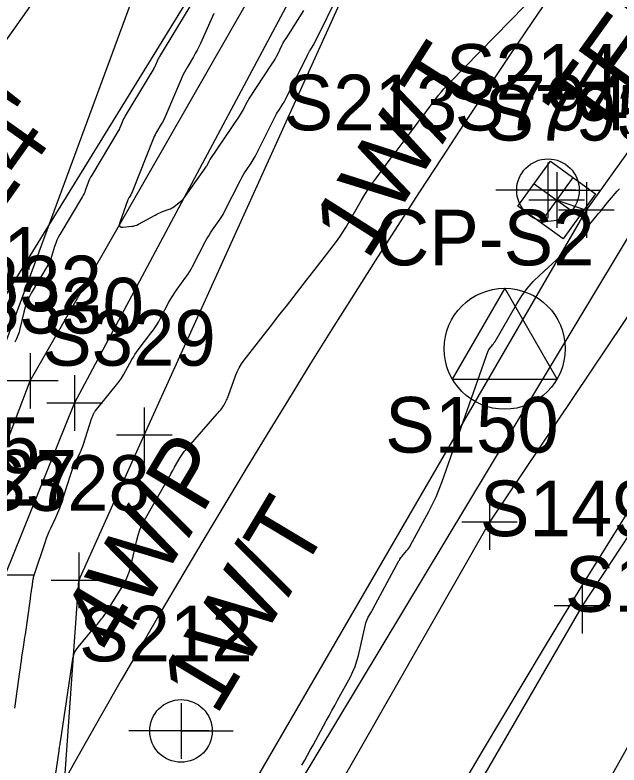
# Model space of a CAD drawing. Extents: x 816928 to 825690, y 436959 to 448212.
# Drawn here: x 818891.9 to 818935.3, y 445110 to 445164 of the extents above; entities that cross this region are included whole.
import ezdxf

# ---------------------------------------------------------------- set-up
doc = ezdxf.new("R2010")
doc.units = 0
for name, color, linetype in [('SURVEY - CENTERLINE - Preliminary', 7, 'Continuous'), ('SURVEY - CONTOURS - Index with Text', 7, 'Continuous'), ('SURVEY - CONTOURS - Intermediate with optional Text', 7, 'Continuous'), ('SURVEY - CONTROL with Text', 7, 'Continuous'), ('SURVEY - DRAINAGE - Area Shapes', 7, 'Continuous'), ('SURVEY - DRAINAGE - Bridges Text', 7, 'Continuous'), ('SURVEY - DTM - Breaklines', 7, 'Continuous'), ('SURVEY - DTM - Breaklines - Points - Locators', 7, 'Continuous'), ('SURVEY - DTM - Breaklines - Points - Numbers', 7, 'Continuous'), ('SURVEY - PROPERTY - Parcels', 7, 'Continuous'), ('SURVEY - PROPERTY - ROW Lines', 7, 'Continuous'), ('SURVEY - TRANSPORTATION - Roads', 7, 'Continuous'), ('SURVEY - TRANSPORTATION - Roads - Points - Locators', 7, 'Continuous'), ('SURVEY - TRANSPORTATION - Roads - Points - Numbers', 7, 'Continuous'), ('SURVEY - UTILITIES - Gas with Text', 7, 'Continuous'), ('SURVEY - UTILITIES - Poles and Miscellaneous - Points - Locators', 7, 'Continuous'), ('SURVEY - UTILITIES - Poles and Miscellaneous - Points - Numbers', 7, 'Continuous'), ('SURVEY - UTILITIES - Poles and Miscellaneous with Text', 7, 'Continuous'), ('SURVEY - UTILITIES - Telephone (Underground) - Points - Locators', 7, 'Continuous'), ('SURVEY - UTILITIES - Telephone (Underground) - Points - Numbers', 7, 'Continuous'), ('SURVEY - UTILITIES - Telephone (Underground) with Text', 7, 'Continuous'), ('SURVEY - VEGETATION - Features with Text', 7, 'Continuous')]:
    doc.layers.add(name, color=color, linetype=linetype)

msp = doc.modelspace()

# ---------------------------------------------------------------- linework, layer by layer
at = {"layer": 'SURVEY - CENTERLINE - Preliminary'}
msp.add_arc((819561.099, 444735.998), 738, 144.598464, 158.728454, dxfattribs=at)
msp.add_arc((819561.099, 444735.998), 738, 144.598464, 158.728454, dxfattribs=at)
at = {"layer": 'SURVEY - CONTOURS - Index with Text'}
msp.add_lwpolyline([(818894.431, 445106.853), (818895.057, 445111.046), (818895.067, 445111.111), (818895.076, 445111.176), (818895.086, 445111.241), (818895.095, 445111.307), (818895.125, 445111.52), (818895.131, 445111.566), (818895.138, 445111.612), (818895.145, 445111.657), (818895.151, 445111.703), (818895.85, 445116.369), (818895.853, 445116.386), (818895.855, 445116.403), (818895.858, 445116.42), (818895.86, 445116.437), (818895.868, 445116.494), (818895.87, 445116.506), (818895.872, 445116.518), (818895.874, 445116.53), (818895.875, 445116.542), (818896.044, 445117.663), (818896.095, 445117.897), (818896.176, 445118.117), (818896.287, 445118.323), (818896.428, 445118.517), (818897.433, 445119.72), (818897.528, 445119.833), (818897.623, 445119.947), (818897.717, 445120.06), (818897.812, 445120.173), (818898.121, 445120.543), (818898.186, 445120.623), (818898.248, 445120.706), (818898.308, 445120.79), (818898.365, 445120.876), (818899.535, 445122.721), (818899.768, 445123.124), (818899.963, 445123.543), (818900.122, 445123.976), (818900.244, 445124.425), (818900.645, 445126.195), (818900.744, 445126.569), (818900.87, 445126.933), (818901.023, 445127.286), (818901.202, 445127.629), (818902.934, 445130.658), (818902.978, 445130.735), (818903.021, 445130.812), (818903.064, 445130.89), (818903.107, 445130.968), (818903.244, 445131.223), (818903.274, 445131.278), (818903.304, 445131.332), (818903.334, 445131.386), (818903.365, 445131.44), (818903.766, 445132.142), (818903.855, 445132.29), (818903.952, 445132.433), (818904.056, 445132.57), (818904.167, 445132.703), (818906.606, 445135.469), (818906.689, 445135.569), (818906.766, 445135.673), (818906.838, 445135.781), (818906.903, 445135.893), (818907.105, 445136.267), (818907.147, 445136.348), (818907.185, 445136.43), (818907.221, 445136.514), (818907.253, 445136.599), (818907.753, 445138.018), (818907.872, 445138.316), (818908.013, 445138.601), (818908.177, 445138.874), (818908.364, 445139.134), (818910.002, 445141.234), (818910.353, 445141.684), (818910.704, 445142.134), (818911.055, 445142.584), (818911.406, 445143.035), (818912.607, 445144.574), (818912.865, 445144.904), (818913.122, 445145.234), (818913.38, 445145.564), (818913.637, 445145.894), (818914.783, 445147.363), (818915.023, 445147.682), (818915.251, 445148.008), (818915.468, 445148.342), (818915.674, 445148.683), (818916.81, 445150.643), (818917.059, 445151.059), (818917.321, 445151.467), (818917.595, 445151.866), (818917.881, 445152.258), (818918.882, 445153.585), (818919.096, 445153.869), (818919.31, 445154.154), (818919.525, 445154.438), (818919.739, 445154.722), (818920.695, 445155.99), (818920.9, 445156.262), (818921.105, 445156.534), (818921.31, 445156.805), (818921.514, 445157.077), (818922.354, 445158.191), (818922.538, 445158.426), (818922.729, 445158.655), (818922.927, 445158.878), (818923.133, 445159.094), (818928.598, 445164.656)], dxfattribs=at)
at = {"layer": 'SURVEY - CONTOURS - Intermediate with optional Text'}
for points in [[(818891.866, 445114.122), (818891.89, 445114.292), (818892.234, 445116.73), (818892.272, 445116.997), (818892.311, 445117.265), (818892.35, 445117.532), (818892.39, 445117.799), (818892.521, 445118.672), (818892.549, 445118.86), (818892.577, 445119.047), (818892.604, 445119.234), (818892.631, 445119.421), (818892.993, 445121.987), (818893.007, 445122.091), (818893.022, 445122.194), (818893.038, 445122.298), (818893.053, 445122.402), (818893.104, 445122.74), (818893.115, 445122.813), (818893.126, 445122.885), (818893.136, 445122.958), (818893.147, 445123.03), (818893.198, 445123.392), (818893.211, 445123.469), (818893.227, 445123.546), (818893.246, 445123.621), (818893.269, 445123.696), (818894.074, 445126.099), (818894.161, 445126.345), (818894.255, 445126.588), (818894.356, 445126.829), (818894.465, 445127.066), (818894.832, 445127.836), (818894.908, 445128.002), (818894.979, 445128.171), (818895.044, 445128.341), (818895.103, 445128.514), (818895.896, 445130.945), (818895.972, 445131.166), (818896.056, 445131.384), (818896.146, 445131.599), (818896.244, 445131.811), (818896.574, 445132.498), (818896.642, 445132.647), (818896.705, 445132.797), (818896.762, 445132.95), (818896.814, 445133.105), (818897.387, 445134.918), (818897.407, 445134.976), (818897.428, 445135.034), (818897.452, 445135.09), (818897.477, 445135.146), (818897.565, 445135.326), (818897.584, 445135.364), (818897.606, 445135.4), (818897.63, 445135.436), (818897.656, 445135.47), (818899.196, 445137.377), (818899.375, 445137.609), (818899.543, 445137.849), (818899.7, 445138.096), (818899.845, 445138.35), (818900.303, 445139.194), (818900.404, 445139.372), (818900.512, 445139.546), (818900.627, 445139.716), (818900.749, 445139.882), (818901.663, 445141.077), (818901.854, 445141.337), (818902.033, 445141.604), (818902.2, 445141.878), (818902.357, 445142.16), (818902.963, 445143.303), (818903.096, 445143.545), (818903.239, 445143.782), (818903.39, 445144.014), (818903.549, 445144.24), (818904.181, 445145.107), (818904.313, 445145.294), (818904.437, 445145.487), (818904.554, 445145.684), (818904.664, 445145.886), (818905.579, 445147.65), (818905.698, 445147.871), (818905.825, 445148.088), (818905.959, 445148.3), (818906.1, 445148.509), (818906.572, 445149.182), (818906.671, 445149.328), (818906.764, 445149.477), (818906.852, 445149.629), (818906.934, 445149.785), (818908.114, 445152.098), (818908.206, 445152.274), (818908.305, 445152.446), (818908.408, 445152.615), (818908.517, 445152.781), (818908.881, 445153.319), (818908.957, 445153.435), (818909.029, 445153.554), (818909.097, 445153.675), (818909.161, 445153.798), (818910.556, 445156.577), (818910.626, 445156.712), (818910.7, 445156.845), (818910.778, 445156.976), (818910.86, 445157.104), (818911.132, 445157.52), (818911.19, 445157.61), (818911.244, 445157.701), (818911.295, 445157.794), (818911.344, 445157.889), (818912.924, 445161.082), (818912.974, 445161.181), (818913.028, 445161.278), (818913.083, 445161.374), (818913.142, 445161.468), (818913.337, 445161.774), (818913.378, 445161.84), (818913.417, 445161.907), (818913.454, 445161.976), (818913.489, 445162.045), (818915.23, 445165.606)], [(818904.464, 445164.579), (818902.283, 445160.974), (818902.236, 445160.892), (818902.192, 445160.809), (818902.15, 445160.725), (818902.112, 445160.639), (818901.991, 445160.356), (818901.964, 445160.296), (818901.936, 445160.237), (818901.905, 445160.179), (818901.872, 445160.122), (818899.814, 445156.707), (818899.753, 445156.6), (818899.696, 445156.491), (818899.644, 445156.381), (818899.596, 445156.267), (818899.447, 445155.894), (818899.414, 445155.815), (818899.377, 445155.737), (818899.338, 445155.661), (818899.295, 445155.586), (818897.409, 445152.44), (818897.327, 445152.296), (818897.253, 445152.149), (818897.186, 445151.998), (818897.126, 445151.844), (818896.942, 445151.334), (818896.9, 445151.226), (818896.854, 445151.121), (818896.802, 445151.017), (818896.745, 445150.916), (818895.117, 445148.18), (818895.003, 445147.975), (818894.902, 445147.763), (818894.813, 445147.546), (818894.737, 445147.324), (818894.511, 445146.587), (818894.458, 445146.431), (818894.396, 445146.279), (818894.326, 445146.131), (818894.247, 445145.987), (818893.055, 445143.958), (818892.879, 445143.632), (818892.731, 445143.295), (818892.609, 445142.948), (818892.513, 445142.591), (818892.244, 445141.405), (818892.178, 445141.155), (818892.093, 445140.911), (818891.99, 445140.675), (818891.87, 445140.446)], [(818906.202, 445164.08), (818906.1, 445163.862), (818905.227, 445161.912), (818905.111, 445161.666), (818904.989, 445161.423), (818904.859, 445161.184), (818904.722, 445160.949), (818904.261, 445160.187), (818904.166, 445160.023), (818904.076, 445159.855), (818903.992, 445159.684), (818903.914, 445159.51), (818902.746, 445156.77), (818902.669, 445156.6), (818902.587, 445156.432), (818902.5, 445156.268), (818902.406, 445156.106), (818902.091, 445155.584), (818902.026, 445155.471), (818901.966, 445155.355), (818901.91, 445155.237), (818901.86, 445155.117), (818900.332, 445151.284), (818900.306, 445151.221), (818900.277, 445151.159), (818900.245, 445151.098), (818900.211, 445151.039), (818900.096, 445150.847), (818900.073, 445150.806), (818900.051, 445150.763), (818900.032, 445150.719), (818900.015, 445150.675), (818899.422, 445149.031), (818899.389, 445148.879), (818899.42, 445148.775), (818899.513, 445148.719), (818899.669, 445148.712), (818900.28, 445148.768), (818900.409, 445148.787), (818900.534, 445148.818), (818900.655, 445148.863), (818900.772, 445148.92), (818901.961, 445149.579), (818902.093, 445149.649), (818902.228, 445149.713), (818902.366, 445149.772), (818902.506, 445149.825), (818902.967, 445149.99), (818903.064, 445150.029), (818903.157, 445150.075), (818903.246, 445150.129), (818903.331, 445150.19), (818903.792, 445150.549), (818903.887, 445150.629), (818903.976, 445150.715), (818904.058, 445150.808), (818904.133, 445150.908), (818905.638, 445153.053), (818905.671, 445153.103), (818905.703, 445153.153), (818905.733, 445153.205), (818905.761, 445153.258), (818905.849, 445153.432), (818905.869, 445153.469), (818905.89, 445153.505), (818905.911, 445153.541), (818905.934, 445153.576), (818908.036, 445156.681), (818908.112, 445156.798), (818908.185, 445156.917), (818908.253, 445157.038), (818908.318, 445157.162), (818908.522, 445157.57), (818908.568, 445157.656), (818908.615, 445157.742), (818908.665, 445157.825), (818908.717, 445157.908), (818910.372, 445160.43), (818910.485, 445160.607), (818910.592, 445160.787), (818910.693, 445160.971), (818910.789, 445161.158), (818911.093, 445161.772), (818911.16, 445161.903), (818911.231, 445162.032), (818911.305, 445162.159), (818911.382, 445162.284), (818912.657, 445164.28)], [(818912.528, 445110.012), (818912.727, 445110.376), (818912.927, 445110.741), (818913.126, 445111.105), (818913.325, 445111.469), (818914.274, 445113.204), (818914.477, 445113.576), (818914.68, 445113.948), (818914.884, 445114.319), (818915.087, 445114.691), (818916.012, 445116.381), (818916.196, 445116.749), (818916.354, 445117.126), (818916.486, 445117.514), (818916.59, 445117.911), (818917.094, 445120.135), (818917.127, 445120.259), (818917.169, 445120.38), (818917.219, 445120.497), (818917.279, 445120.61), (818917.487, 445120.975), (818917.532, 445121.054), (818917.576, 445121.133), (818917.619, 445121.211), (818917.663, 445121.291), (818919.507, 445124.705), (818919.525, 445124.738), (818919.544, 445124.771), (818919.562, 445124.804), (818919.581, 445124.837), (818919.642, 445124.945), (818919.656, 445124.967), (818919.671, 445124.989), (818919.687, 445125.01), (818919.704, 445125.031), (818920.072, 445125.448), (818920.148, 445125.54), (818920.219, 445125.635), (818920.284, 445125.734), (818920.343, 445125.837), (818921.657, 445128.262), (818921.928, 445128.786), (818922.177, 445129.32), (818922.406, 445129.863), (818922.613, 445130.415), (818925.925, 445139.805), (818925.94, 445139.842), (818925.958, 445139.878), (818925.979, 445139.912), (818926.002, 445139.945), (818926.083, 445140.049), (818926.101, 445140.072), (818926.118, 445140.094), (818926.136, 445140.116), (818926.153, 445140.139), (818926.231, 445140.239), (818926.248, 445140.26), (818926.265, 445140.282), (818926.281, 445140.303), (818926.298, 445140.325), (818926.366, 445140.412), (818926.38, 445140.43), (818926.394, 445140.45), (818926.406, 445140.47), (818926.419, 445140.49), (818927.986, 445143.195), (818928.342, 445143.759), (818928.737, 445144.291), (818929.171, 445144.792), (818929.645, 445145.261), (818931.729, 445147.179), (818931.896, 445147.338), (818932.057, 445147.503), (818932.212, 445147.673), (818932.362, 445147.849), (818932.84, 445148.432), (818932.942, 445148.557), (818933.044, 445148.682), (818933.147, 445148.807), (818933.249, 445148.931), (818933.865, 445149.683), (818933.997, 445149.844), (818934.129, 445150.006), (818934.261, 445150.167), (818934.394, 445150.328), (818935.059, 445151.14), (818935.208, 445151.306), (818935.369, 445151.459)]]:
    msp.add_lwpolyline(points, dxfattribs=at)
at = {"layer": 'SURVEY - CONTROL with Text'}
for p, q in [((818927.112, 445144.312), (818923.345, 445137.787)), ((818930.88, 445137.787), (818927.112, 445144.312)), ((818927.112, 445139.962), (818927.112, 445139.962)), ((818923.345, 445137.787), (818930.88, 445137.787))]:
    msp.add_line(p, q, dxfattribs=at)
msp.add_circle((818927.112, 445139.962), 4.35, dxfattribs=at)
at = {"layer": 'SURVEY - DRAINAGE - Area Shapes'}
msp.add_arc((819561.099, 444735.998), 738, 144.598464, 158.728454, dxfattribs=at)
at = {"layer": 'SURVEY - DRAINAGE - Bridges Text'}
msp.add_line((818898.784, 445172.789), (818877.079, 445142.249), dxfattribs=at)
at = {"layer": 'SURVEY - DTM - Breaklines'}
for points in [[(818668.595, 444528.248), (818685.72, 444574.968), (818701.794, 444621.45), (818719.062, 444668.194), (818736.238, 444715.249), (818753.948, 444762.85), (818774.464, 444810.969), (818792.449, 444864.448), (818805.628, 444902.916), (818824.667, 444952.978), (818842.703, 444999.992), (818860.037, 445043.657), (818874.783, 445092.697), (818880.828, 445100.462), (818882.708, 445127.319), (818888.697, 445139.719), (818911.769, 445177.181)], [(818808.76, 444902.23), (818827.799, 444952.151), (818848.589, 444997.649), (818865.395, 445041.972), (818883.078, 445086.424), (818886.189, 445099.702), (818888.533, 445126.027), (818892.982, 445137.658), (818915.716, 445177.345)], [(818674.595, 444526.594), (818691.482, 444572.447), (818707.878, 444620.16), (818723.912, 444667.229), (818740.639, 444713.784), (818759.184, 444760.748), (818780.007, 444808.946), (818796, 444863.508), (818810.795, 444901.838), (818829.914, 444950.597), (818849.199, 444995.994), (818867.147, 445042.084), (818885.66, 445087.698), (818887.911, 445097.82), (818891.186, 445123.694), (818896.177, 445136.062), (818917.377, 445175.791)], [(818676.308, 444526.27), (818695.981, 444570.723), (818712.39, 444618.98), (818728.83, 444665.288), (818745.895, 444712.28), (818764.807, 444759.048), (818784.52, 444806.667), (818801.14, 444861.811), (818818.983, 444900.087), (818838.243, 444946.217), (818855.869, 444992.165), (818873.704, 445038.582), (818892.288, 445085.577), (818894.59, 445096.559), (818896.482, 445123.312), (818901.189, 445133.745), (818919.534, 445174.233), (818947.165, 445168.058)], [(818958.139, 445160.069), (818932.682, 445121.487), (818907.758, 445078.468), (818886.279, 445033.29), (818867.243, 444986.881), (818848.651, 444941.091), (818830.333, 444893.785), (818812.367, 444847.898), (818794.091, 444801.186), (818775.412, 444755.123), (818757.321, 444708.609), (818740.17, 444661.598), (818740.227, 444661.382), (818723.384, 444614.358), (818707.23, 444567.59), (818689.196, 444521.032)]]:
    msp.add_lwpolyline(points, dxfattribs=at)
at = {"layer": 'SURVEY - DTM - Breaklines - Points - Locators'}
for p, q in [((818892.982, 445139.658), (818892.982, 445135.658)), ((818896.177, 445138.062), (818896.177, 445134.062)), ((818894.982, 445137.658), (818890.982, 445137.658)), ((818898.177, 445136.062), (818894.177, 445136.062)), ((818901.189, 445135.745), (818901.189, 445131.745)), ((818903.189, 445133.745), (818899.189, 445133.745)), ((818896.482, 445125.312), (818896.482, 445121.312)), ((818893.186, 445123.694), (818889.186, 445123.694)), ((818932.682, 445123.487), (818932.682, 445119.487)), ((818898.482, 445123.312), (818894.482, 445123.312)), ((818934.682, 445121.487), (818930.682, 445121.487))]:
    msp.add_line(p, q, dxfattribs=at)
at = {"layer": 'SURVEY - PROPERTY - Parcels'}
for radius in [763, 713]:
    msp.add_arc((819561.099, 444735.998), radius, 144.598464, 158.728454, dxfattribs=at)
at = {"layer": 'SURVEY - PROPERTY - ROW Lines'}
for radius in [763, 763, 713, 713]:
    msp.add_arc((819561.099, 444735.998), radius, 144.598464, 158.728454, dxfattribs=at)
at = {"layer": 'SURVEY - TRANSPORTATION - Roads'}
for points in [[(818965.229, 445155.363), (818951.411, 445165.352), (818926.02, 445127.499), (818900.328, 445082.499), (818878.311, 445036.446), (818858.824, 444990.147), (818840.564, 444944.187), (818822.719, 444897.894), (818804.417, 444851.441), (818785.945, 444804.727), (818767.422, 444758.087), (818749.481, 444712.19), (818731.94, 444664.32), (818715.455, 444617.821), (818698.912, 444570.495), (818680.86, 444523.941)], [(818965.229, 445155.363), (818938.616, 445116.052), (818915.349, 445074.624), (818893.365, 445028.079), (818874.295, 444982.228), (818856.423, 444936.819), (818838.526, 444889.933), (818820.316, 444844.098), (818801.626, 444797.247), (818782.894, 444750.293), (818765.195, 444704.769), (818748.054, 444657.938), (818731.68, 444611.01), (818715.158, 444564.483), (818697.018, 444517.159)], [(818965.229, 445155.363), (818938.616, 445116.052), (818915.349, 445074.624), (818898.78, 445039.544), (818893.365, 445028.079), (818891.235, 445022.959), (818874.295, 444982.228), (818856.423, 444936.819), (818838.526, 444889.933), (818820.316, 444844.098), (818801.626, 444797.247), (818782.894, 444750.293), (818765.195, 444704.769), (818757.626, 444684.091), (818748.679, 444659.647), (818748.054, 444657.938), (818731.68, 444611.01), (818715.158, 444564.483), (818697.018, 444517.159)]]:
    msp.add_lwpolyline(points, dxfattribs=at)
at = {"layer": 'SURVEY - TRANSPORTATION - Roads - Points - Locators'}
for p, q in [((818926.02, 445129.499), (818926.02, 445125.499)), ((818928.02, 445127.499), (818924.02, 445127.499))]:
    msp.add_line(p, q, dxfattribs=at)
at = {"layer": 'SURVEY - UTILITIES - Gas with Text'}
msp.add_lwpolyline([(818677.986, 444524.549), (818704.191, 444595.26), (818728.998, 444664.068), (818764.629, 444758.415), (818803.581, 444855.269), (818837.396, 444944.843), (818872.359, 445029.489), (818905.906, 445097.999), (818946.069, 445164.692)], dxfattribs=at)
at = {"layer": 'SURVEY - UTILITIES - Poles and Miscellaneous - Points - Locators'}
for p, q in [((818930.225, 445153.366), (818930.225, 445149.366)), ((818932.225, 445151.366), (818928.225, 445151.366)), ((818903.83, 445114.488), (818903.83, 445110.488)), ((818905.83, 445112.488), (818901.83, 445112.488))]:
    msp.add_line(p, q, dxfattribs=at)
at = {"layer": 'SURVEY - UTILITIES - Poles and Miscellaneous with Text'}
for p, q in [((818930.225, 445151.366), (818926.475, 445151.366)), ((818930.225, 445151.366), (818933.975, 445151.366)), ((818903.83, 445112.488), (818900.08, 445112.488)), ((818903.83, 445112.488), (818907.58, 445112.488))]:
    msp.add_line(p, q, dxfattribs=at)
for centre in [(818930.225, 445151.366), (818903.83, 445112.488)]:
    msp.add_circle(centre, 2.25, dxfattribs=at)
at = {"layer": 'SURVEY - UTILITIES - Telephone (Underground) - Points - Locators'}
for p, q in [((818930.857, 445152.66), (818930.857, 445148.66)), ((818932.026, 445152.283), (818929.688, 445149.037)), ((818929.234, 445151.829), (818932.48, 445149.491)), ((818932.992, 445151.937), (818932.992, 445147.937)), ((818932.992, 445151.937), (818932.992, 445147.937)), ((818932.857, 445150.66), (818928.857, 445150.66)), ((818934.992, 445149.937), (818930.992, 445149.937)), ((818934.992, 445149.937), (818930.992, 445149.937))]:
    msp.add_line(p, q, dxfattribs=at)
at = {"layer": 'SURVEY - UTILITIES - Telephone (Underground) with Text'}
msp.add_line((818898.43, 445090.416), (818932.992, 445149.937), dxfattribs=at)
msp.add_lwpolyline([(818930.857, 445150.66), (818932.992, 445149.937), (818944.966, 445166.651), (818949.519, 445169.463), (818968.39, 445195.328), (818969.083, 445199.507), (818972.238, 445210.883), (818980.303, 445223.767), (818989.561, 445238.187), (819000.76, 445253.257)], dxfattribs=at)
msp.add_lwpolyline([(818931.311, 445147.868), (818928.065, 445150.206), (818930.403, 445153.452), (818933.649, 445151.114)], close=True, dxfattribs=at)
at = {"layer": 'SURVEY - VEGETATION - Features with Text'}
msp.add_lwpolyline([(818921.649, 445531.075), (818911.357, 445419.447), (818895.02, 445347.602), (818900.539, 445320.739), (818919.801, 445285.725), (818871.556, 445256.506), (818910.143, 445268.505), (818928.958, 445242.751), (818875.35, 445097.529)], dxfattribs=at)

# ---------------------------------------------------------------- texts
at = {"layer": 'SURVEY - CONTROL with Text'}
msp.add_text('CP-S2', height=4, dxfattribs=at).set_placement((818917.824, 445145.962))
at = {"layer": 'SURVEY - DRAINAGE - Bridges Text'}
msp.add_text("1.14'", height=5, rotation=54.5985, dxfattribs=at).set_placement((818887.084, 445144.458))
at = {"layer": 'SURVEY - DTM - Breaklines - Points - Numbers'}
for s, p in [('S331', (818881.518, 445144.719)), ('S332', (818885.646, 445142.658)), ('S330', (818888.668, 445141.062)), ('S329', (818893.837, 445138.745)), ('S325', (818881.197, 445131.027)), ('S327', (818883.85, 445128.694)), ('S328', (818889.099, 445128.312)), ('S149', (818925.33, 445126.487))]:
    msp.add_text(s, height=4, dxfattribs=at).set_placement(p)
at = {"layer": 'SURVEY - TRANSPORTATION - Roads - Points - Numbers'}
for s, p in [('S150', (818918.511, 445132.499)), ('S151', (818931.437, 445121.052))]:
    msp.add_text(s, height=4, dxfattribs=at).set_placement(p)
at = {"layer": 'SURVEY - UTILITIES - Poles and Miscellaneous - Points - Numbers'}
for s, p in [('S214', (818922.889, 445157.866)), ('S212', (818896.494, 445117.488))]:
    msp.add_text(s, height=4, dxfattribs=at).set_placement(p)
at = {"layer": 'SURVEY - UTILITIES - Poles and Miscellaneous with Text'}
for s, rotation, p in [('1W/T', 57.6334, (818917.223, 445146.22)), ('4W/P', 59.1232, (818899.202, 445117.767)), ('1W/T', 59.1232, (818906.354, 445113.491))]:
    msp.add_text(s, height=5, rotation=rotation, dxfattribs=at).set_placement(p)
at = {"layer": 'SURVEY - UTILITIES - Telephone (Underground) - Points - Numbers'}
for s, p in [('S213', (818911.211, 445155.673)), ('S794', (818923.521, 445155.66)), ('S793', (818925.656, 445154.937)), ('S795', (818925.656, 445154.937))]:
    msp.add_text(s, height=4, dxfattribs=at).set_placement(p)
at = {"layer": 'SURVEY - UTILITIES - Telephone (Underground) with Text'}
msp.add_text('TEL. PED.', height=5.0001, rotation=54.2438, dxfattribs=at).set_placement((818933.779, 445154.717))

doc.saveas('drawing.dxf')
